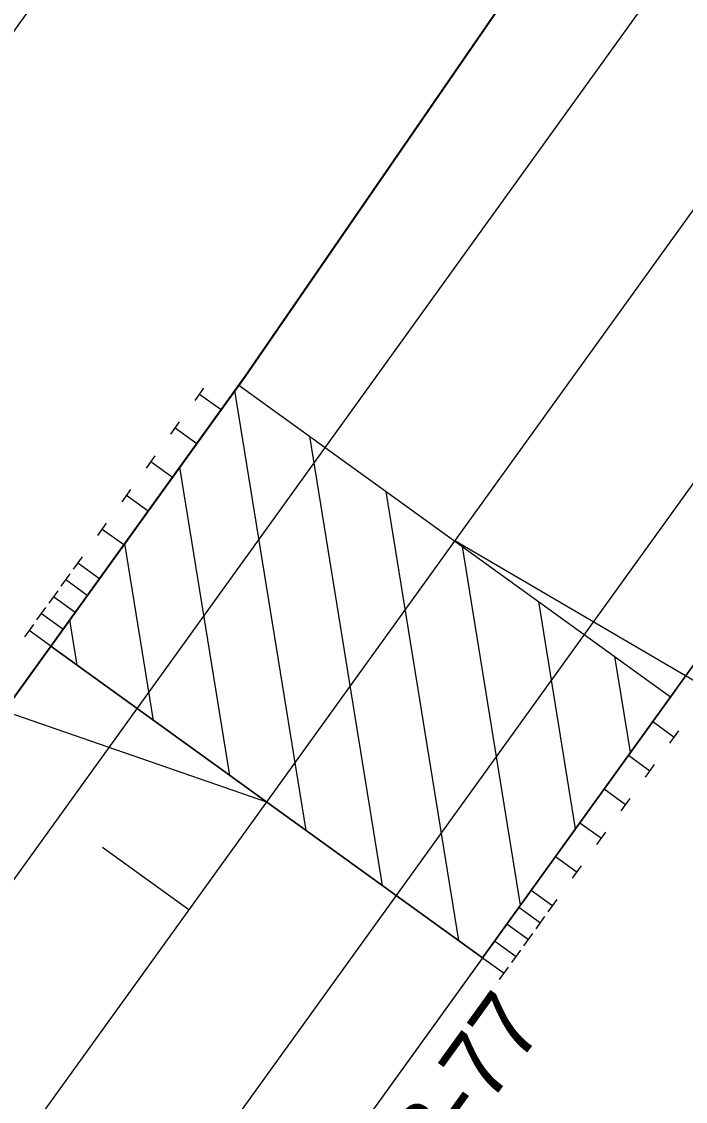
# Model space of a CAD drawing. Extents: x 2189281 to 2191267, y 386656 to 389012.
# Drawn here: x 2190394.2 to 2190444.1, y 387975.4 to 388056.4 of the extents above; entities that cross this region are included whole.
import ezdxf

# ---------------------------------------------------------------- set-up
doc = ezdxf.new("R2010")
doc.units = 0
for name, color, linetype in [('Prop Approach Slab', 7, 'Continuous'), ('Prop Approach Slab Hatching', 7, 'Continuous'), ('Prop Conc Shoulder Berm Gutter', 7, 'Continuous'), ('Prop DSN Text', 7, 'Continuous'), ('Prop EOT', 7, 'Continuous'), ('Prop Guardrail', 7, 'Continuous'), ('Prop Guardrail Anchor Unit CELL', 7, 'Continuous'), ('Prop Horizontal Alignment', 7, 'Continuous'), ('Prop Horizontal Alignment Tick Large', 7, 'Continuous'), ('Prop Paved Shoulder', 7, 'Continuous'), ('Prop Roadway Bridge', 7, 'Continuous'), ('Prop Structure Anchor Unit CELL', 7, 'Continuous'), ('Scratch_Level_6', 7, 'Continuous')]:
    doc.layers.add(name, color=color, linetype=linetype)

msp = doc.modelspace()

# ---------------------------------------------------------------- linework, layer by layer
at = {"layer": 'Prop Approach Slab'}
msp.add_lwpolyline([(2190396.396, 388009.54), (2190410.537, 388029.142), (2190442.98, 388005.745), (2190428.839, 387986.143)], close=True, dxfattribs=at)
at = {"layer": 'Prop Approach Slab Hatching'}
for p, q in [((2190415.589, 387995.699), (2190410.237, 388028.733)), ((2190421.324, 387991.563), (2190415.858, 388025.305)), ((2190409.854, 387999.835), (2190406.101, 388022.998)), ((2190427.059, 387987.427), (2190421.593, 388021.169)), ((2190404.118, 388003.971), (2190401.965, 388017.263)), ((2190431.692, 387990.098), (2190427.328, 388017.032)), ((2190435.828, 387995.833), (2190433.064, 388012.896)), ((2190398.383, 388008.107), (2190397.829, 388011.527)), ((2190439.964, 388001.569), (2190438.799, 388008.76))]:
    msp.add_line(p, q, dxfattribs=at)
at = {"layer": 'Prop Conc Shoulder Berm Gutter'}
for p, q in [((2190437.141, 388067.727), (2190410.549, 388029.134)), ((2190470.37, 388043.73), (2190442.977, 388005.747))]:
    msp.add_line(p, q, dxfattribs=at)
at = {"layer": 'Prop DSN Text'}
for points in [[(2190288.262, 388037.683), (2190290.51, 388040.127), (2190412.618, 387997.842)], [(2190687.031, 387855.754), (2190691.854, 387862.416), (2190426.756, 388017.446)]]:
    msp.add_lwpolyline(points, dxfattribs=at)
at = {"layer": 'Prop EOT'}
msp.add_line((2190192.309, 387712.871), (2190484.775, 388118.412), dxfattribs=at)
msp.add_lwpolyline([(2190181.763, 387658.831), (2190211.775, 387698.833), (2190504.241, 388104.374), (2190532.845, 388145.392)], dxfattribs=at)
at = {"layer": 'Prop Guardrail'}
for points in [[(2190453.169, 388090.989), (2190411.019, 388029.817), (2190409.776, 388028.094)], [(2190442.22, 388004.697), (2190470.072, 388043.317)]]:
    msp.add_lwpolyline(points, dxfattribs=at)
at = {"layer": 'Prop Horizontal Alignment'}
msp.add_line((2189529.371, 386773.107), (2190699.234, 388395.272), dxfattribs=at)
msp.add_arc((2192257.949, 386708.79), 2300, 135.254986, 144.201843, dxfattribs=at)
at = {"layer": 'Prop Horizontal Alignment Tick Large'}
msp.add_line((2190406.768, 387989.731), (2190400.28, 387994.41), dxfattribs=at)
at = {"layer": 'Prop Paved Shoulder'}
for p, q in [((2190411.019, 388029.817), (2190288.669, 387860.163)), ((2190443.463, 388006.42), (2190321.112, 387836.766))]:
    msp.add_line(p, q, dxfattribs=at)
msp.add_lwpolyline([(2190467.532, 388110.906), (2190453.169, 388090.989), (2190424.64, 388049.585)], dxfattribs=at)
at = {"layer": 'Prop Roadway Bridge'}
msp.add_lwpolyline([(2190302.807, 387879.767), (2190396.396, 388009.54), (2190428.839, 387986.143), (2190335.25, 387856.37)], close=True, dxfattribs=at)
at = {"layer": 'Prop Structure Anchor Unit CELL'}
for p, q in [((2190407.234, 388027.988), (2190407.904, 388028.917)), ((2190396.396, 388009.54), (2190409.776, 388028.094)), ((2190409.191, 388027.283), (2190407.569, 388028.453)), ((2190405.406, 388025.453), (2190406.076, 388026.383)), ((2190407.364, 388024.748), (2190405.741, 388025.918)), ((2190403.578, 388022.919), (2190404.248, 388023.848)), ((2190405.536, 388022.213), (2190403.913, 388023.383)), ((2190401.751, 388020.384), (2190402.421, 388021.313)), ((2190403.708, 388019.679), (2190402.086, 388020.849)), ((2190399.923, 388017.85), (2190400.593, 388018.779)), ((2190401.88, 388017.144), (2190400.258, 388018.314)), ((2190398.095, 388015.315), (2190398.765, 388016.244)), ((2190400.052, 388014.61), (2190398.43, 388015.779)), ((2190397.181, 388014.048), (2190397.851, 388014.977)), ((2190399.138, 388013.342), (2190397.516, 388014.512)), ((2190396.267, 388012.78), (2190396.937, 388013.709)), ((2190398.224, 388012.075), (2190396.602, 388013.245)), ((2190395.353, 388011.513), (2190396.023, 388012.442)), ((2190397.31, 388010.808), (2190395.688, 388011.978)), ((2190394.439, 388010.246), (2190395.109, 388011.175)), ((2190396.396, 388009.54), (2190394.774, 388010.71)), ((2190428.839, 387986.143), (2190442.22, 388004.697)), ((2190441.635, 388003.885), (2190443.257, 388002.716)), ((2190442.922, 388002.251), (2190443.592, 388003.18)), ((2190439.807, 388001.351), (2190441.429, 388000.181)), ((2190441.094, 387999.716), (2190441.764, 388000.646)), ((2190437.979, 387998.816), (2190439.601, 387997.646)), ((2190439.266, 387997.182), (2190439.936, 387998.111)), ((2190436.151, 387996.282), (2190437.773, 387995.112)), ((2190437.438, 387994.647), (2190438.108, 387995.576)), ((2190434.323, 387993.747), (2190435.945, 387992.577)), ((2190435.61, 387992.113), (2190436.28, 387993.042)), ((2190432.495, 387991.212), (2190434.117, 387990.042)), ((2190433.782, 387989.578), (2190434.452, 387990.507)), ((2190431.581, 387989.945), (2190433.203, 387988.775)), ((2190432.868, 387988.311), (2190433.538, 387989.24)), ((2190430.667, 387988.678), (2190432.289, 387987.508)), ((2190429.753, 387987.41), (2190431.376, 387986.241)), ((2190431.954, 387987.043), (2190432.624, 387987.972)), ((2190431.04, 387985.776), (2190431.711, 387986.705)), ((2190428.839, 387986.143), (2190430.462, 387984.973)), ((2190430.127, 387984.509), (2190430.797, 387985.438))]:
    msp.add_line(p, q, dxfattribs=at)
at = {"layer": 'Scratch_Level_6'}
for points in [[(2190396.388, 388009.546), (2190411.011, 388029.823), (2190453.161, 388090.994)], [(2190428.847, 387986.137), (2190443.471, 388006.414), (2190470.08, 388043.311), (2190498.179, 388080.676)]]:
    msp.add_lwpolyline(points, dxfattribs=at)

# ---------------------------------------------------------------- texts
at = {"layer": 'Prop Guardrail Anchor Unit CELL'}
msp.add_text('B-77', height=5, rotation=54.20184, dxfattribs=at).set_placement((2190425.426, 387969.618))

doc.saveas('drawing.dxf')
